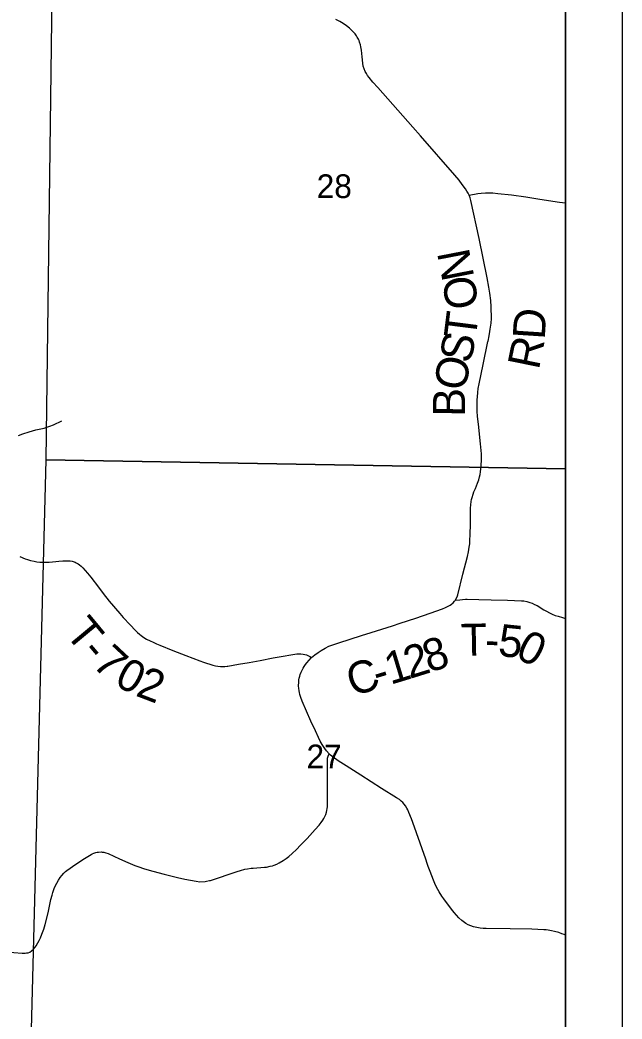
# Model space of a CAD drawing. Extents: x 0 to 34, y 0 to 22.
# Drawn here: x 7.936 to 9, y 15.399 to 17.164 of the extents above; entities that cross this region are included whole.
import ezdxf

# ---------------------------------------------------------------- set-up
doc = ezdxf.new("R2010")
doc.units = 0
for name, color, linetype in [('GM_X_Corporation', 7, 'Continuous'), ('GM_X_County_Road', 7, 'Continuous'), ('GM_X_County_Road_Text', 7, 'Continuous'), ('GM_X_Section_Text', 7, 'Continuous'), ('GM_X_Township_Road', 7, 'Continuous'), ('GM_X_Township_Road_Text', 7, 'Continuous'), ('GM_X_Township_Text', 7, 'Continuous'), ('SH_Data', 7, 'Continuous')]:
    doc.layers.add(name, color=color, linetype=linetype)

msp = doc.modelspace()

# ---------------------------------------------------------------- linework, layer by layer
at = {"layer": 'GM_X_Corporation'}
for points in [[(7.1227, 14.1), (8.9, 14.1), (8.9, 20.9), (7.231, 20.9), (7.2244, 20.2649), (7.1982, 19.2496), (7.1981, 19.2461), (7.1974, 19.2018), (7.1957, 19.0991), (7.1992, 18.9556), (7.197, 18.9465), (7.1949, 18.8464), (7.1846, 18.5133), (7.1817, 18.3306), (7.1804, 18.2238), (7.1572, 17.4131), (7.1504, 16.6562), (7.1434, 16.3848), (7.1318, 15.4937)], [(8.9, 16.3711), (8.9, 17.3865), (7.9945, 17.3927), (7.9815, 16.3875)], [(8.9, 15.3661), (8.9, 16.3711), (7.9815, 16.3875), (7.9552, 15.3809)]]:
    msp.add_lwpolyline(points, close=True, dxfattribs=at)
at = {"layer": 'GM_X_County_Road'}
for points in [[(8.7297, 16.8547), (8.7277, 16.8587), (8.7258, 16.8622), (8.7235, 16.8659), (8.7175, 16.8738), (8.7119, 16.8815), (8.7045, 16.8904), (8.6435, 16.9599), (8.6301, 16.9751), (8.5681, 17.045), (8.5597, 17.0546), (8.553, 17.0629), (8.5502, 17.0665), (8.548, 17.0698), (8.5461, 17.0734), (8.5441, 17.078), (8.5426, 17.0829), (8.5417, 17.0879), (8.5407, 17.0994), (8.5401, 17.1053), (8.5394, 17.111), (8.5383, 17.1168), (8.5375, 17.1203), (8.536, 17.1253), (8.535, 17.128), (8.5339, 17.1304), (8.5318, 17.1343), (8.5307, 17.1361), (8.528, 17.1399), (8.523, 17.1454), (8.5179, 17.1497), (8.5127, 17.1539), (8.5069, 17.1579), (8.501, 17.1615), (8.4942, 17.1652)], [(8.7297, 16.8547), (8.7453, 16.8577), (8.7508, 16.8584), (8.7585, 16.8589), (8.7671, 16.859), (8.7718, 16.8588), (8.7805, 16.8581), (8.8047, 16.8553), (8.8297, 16.8518), (8.8548, 16.848), (8.8897, 16.8427), (8.9, 16.8414)], [(8.9, 15.5472), (8.8974, 15.5484), (8.8936, 15.55), (8.8884, 15.5519), (8.8805, 15.5542), (8.8753, 15.5554), (8.8696, 15.5564), (8.8658, 15.5569), (8.8619, 15.5571), (8.8403, 15.5578), (8.8021, 15.5584), (8.7595, 15.5593), (8.7544, 15.5595), (8.7492, 15.56), (8.7434, 15.561), (8.7376, 15.5624), (8.7327, 15.5639), (8.7281, 15.5658), (8.7239, 15.568), (8.7214, 15.5697), (8.717, 15.5731), (8.7113, 15.5781), (8.7033, 15.5873), (8.6985, 15.5934), (8.685, 15.6114), (8.6814, 15.6166), (8.6765, 15.6241), (8.6722, 15.6323), (8.6692, 15.6387), (8.6667, 15.6446), (8.6608, 15.6597), (8.6595, 15.6631), (8.6574, 15.669), (8.6557, 15.6739), (8.6531, 15.6819), (8.6369, 15.7282), (8.6333, 15.7384), (8.6277, 15.7533), (8.6233, 15.764), (8.6211, 15.7687), (8.6194, 15.7718), (8.6169, 15.7762), (8.6147, 15.7792), (8.6124, 15.7818), (8.6098, 15.7841), (8.6063, 15.7869), (8.6012, 15.7903), (8.5747, 15.8068), (8.5383, 15.8304), (8.5123, 15.8465), (8.4981, 15.8557), (8.4891, 15.8621), (8.4847, 15.8654), (8.482, 15.8676), (8.4777, 15.8729), (8.4744, 15.8775), (8.4697, 15.8846), (8.4666, 15.8903), (8.4635, 15.8966), (8.458, 15.9086), (8.4501, 15.9257), (8.4345, 15.9609), (8.4319, 15.9676), (8.4305, 15.9726), (8.4297, 15.976), (8.4291, 15.9793), (8.4284, 15.9836), (8.4282, 15.9874), (8.4284, 15.9951), (8.4288, 15.9985), (8.4293, 16.0013), (8.4303, 16.0052), (8.4312, 16.0081), (8.4328, 16.0124), (8.4349, 16.0167), (8.4365, 16.0194), (8.4381, 16.0221), (8.4406, 16.0258), (8.4427, 16.0285), (8.4467, 16.0334), (8.451, 16.0378), (8.457, 16.0428), (8.4627, 16.0468), (8.4681, 16.0504), (8.475, 16.0544), (8.4818, 16.0578), (8.4904, 16.0611), (8.4995, 16.0642), (8.5392, 16.0771), (8.5563, 16.0824), (8.5943, 16.0941), (8.608, 16.0985), (8.6356, 16.1077), (8.6609, 16.1162), (8.6827, 16.1238), (8.6879, 16.1261), (8.6925, 16.1285), (8.6959, 16.1305), (8.6986, 16.1324), (8.7015, 16.1349), (8.7041, 16.1377), (8.7053, 16.1393), (8.7064, 16.1413), (8.7084, 16.1454), (8.7096, 16.149), (8.7184, 16.185), (8.7267, 16.2163), (8.7285, 16.2245), (8.7299, 16.2327), (8.7307, 16.239), (8.7311, 16.2443), (8.7317, 16.2561), (8.7319, 16.273), (8.7318, 16.2981), (8.7319, 16.3019), (8.7324, 16.3078), (8.7333, 16.3138), (8.7341, 16.3173), (8.735, 16.321), (8.7368, 16.3267), (8.7382, 16.3307), (8.7409, 16.3365), (8.7428, 16.3411), (8.7446, 16.3461), (8.7467, 16.3522), (8.7481, 16.3572), (8.7491, 16.3614), (8.7499, 16.3662), (8.7505, 16.3712), (8.7512, 16.3792), (8.7515, 16.3856), (8.7513, 16.398), (8.7499, 16.4153), (8.746, 16.4502), (8.7447, 16.464), (8.7441, 16.4733), (8.7437, 16.4835), (8.744, 16.4935), (8.7443, 16.4984), (8.7451, 16.5065), (8.7459, 16.5133), (8.7473, 16.5217), (8.7543, 16.5557), (8.763, 16.5966), (8.7632, 16.5972), (8.765, 16.6066), (8.7664, 16.6139), (8.7671, 16.6181), (8.7684, 16.6285), (8.7691, 16.6368), (8.7687, 16.6575), (8.7679, 16.6688), (8.7664, 16.682), (8.7647, 16.6925), (8.7615, 16.7088), (8.7472, 16.7782), (8.7328, 16.8455), (8.7315, 16.8503), (8.7297, 16.8547)]]:
    msp.add_lwpolyline(points, dxfattribs=at)
at = {"layer": 'GM_X_Township_Road'}
for points in [[(7.9329, 16.4302), (7.9408, 16.4333), (7.9521, 16.437), (7.9636, 16.4401), (7.9723, 16.4422), (7.9783, 16.4435), (7.9831, 16.4447), (7.9883, 16.4466), (7.9947, 16.4493), (8.0097, 16.4562)], [(7.9354, 16.2163), (7.9447, 16.2125), (7.949, 16.2111), (7.9543, 16.2095), (7.9609, 16.208), (7.9656, 16.2071), (7.9709, 16.2065), (7.9756, 16.2064), (7.9869, 16.2066), (7.9931, 16.207), (7.999, 16.2075), (8.0044, 16.208), (8.0111, 16.2087), (8.0159, 16.2089), (8.0212, 16.2089), (8.0244, 16.2087), (8.0278, 16.2082), (8.0298, 16.2075), (8.0331, 16.2064), (8.0352, 16.2055), (8.0387, 16.2034), (8.0411, 16.2017), (8.0437, 16.1997), (8.047, 16.1967), (8.055, 16.1871), (8.0608, 16.1797), (8.0743, 16.1622), (8.0825, 16.1513), (8.0935, 16.1374), (8.1119, 16.1156), (8.1178, 16.1089), (8.1303, 16.0955), (8.1398, 16.0856), (8.1434, 16.0822), (8.1471, 16.0792), (8.1501, 16.0769), (8.1547, 16.0736), (8.1593, 16.0706), (8.1655, 16.0673), (8.1708, 16.0649), (8.1771, 16.0622), (8.1828, 16.0598), (8.2061, 16.0507), (8.229, 16.0417), (8.2536, 16.0324), (8.2599, 16.03), (8.2763, 16.0247), (8.2815, 16.0233), (8.2852, 16.0226), (8.2899, 16.0222), (8.2941, 16.0221), (8.2976, 16.0223), (8.3019, 16.0228), (8.3029, 16.023)], [(8.7053, 16.1393), (8.7133, 16.1402), (8.7179, 16.1406), (8.7231, 16.1409), (8.7263, 16.1409), (8.7467, 16.1408), (8.7685, 16.14), (8.7974, 16.1391), (8.8223, 16.1383), (8.8261, 16.1379), (8.8319, 16.1367), (8.8371, 16.1352), (8.841, 16.1338), (8.8454, 16.1319), (8.8497, 16.1297), (8.862, 16.1222), (8.8762, 16.1148), (8.8818, 16.1125), (8.8868, 16.1109), (8.8945, 16.1085), (8.9, 16.1071)], [(8.3029, 16.023), (8.3219, 16.0261), (8.3409, 16.0291), (8.3602, 16.0328), (8.383, 16.0372), (8.4008, 16.0405), (8.4147, 16.043), (8.4216, 16.0441), (8.4248, 16.0443), (8.428, 16.0444), (8.4321, 16.0443), (8.436, 16.044), (8.439, 16.0435), (8.4424, 16.0426), (8.4457, 16.0412), (8.4483, 16.0397), (8.451, 16.0378)], [(7.9098, 15.5179), (7.9395, 15.5159), (7.9446, 15.5158), (7.9474, 15.5161), (7.9502, 15.5165), (7.953, 15.5177), (7.9559, 15.5196), (7.9596, 15.5227), (7.962, 15.5256), (7.9642, 15.5289), (7.9673, 15.5341), (7.9695, 15.5382), (7.972, 15.543), (7.9744, 15.549), (7.9777, 15.5578), (7.9803, 15.5666), (7.9854, 15.5867), (7.9884, 15.6014), (7.9904, 15.6107), (7.9922, 15.618), (7.9936, 15.6227), (7.9963, 15.6301), (7.9978, 15.6338), (8.0005, 15.6394), (8.0036, 15.6446), (8.0068, 15.6493), (8.0094, 15.6527), (8.0133, 15.6571), (8.0161, 15.6597), (8.0182, 15.6617), (8.0341, 15.6731), (8.0494, 15.6828), (8.0613, 15.6898), (8.0631, 15.6909), (8.0659, 15.6921), (8.0697, 15.6934), (8.0721, 15.6939), (8.0746, 15.6943), (8.0789, 15.6945), (8.0808, 15.6944), (8.0837, 15.694), (8.0875, 15.693), (8.0913, 15.6915), (8.1015, 15.687), (8.1114, 15.6824), (8.1263, 15.6758), (8.1384, 15.6708), (8.1456, 15.6682), (8.1538, 15.6653), (8.16, 15.6633), (8.1705, 15.6603), (8.1905, 15.6552), (8.2139, 15.6494), (8.2272, 15.6467), (8.2471, 15.6426), (8.2533, 15.6419), (8.2629, 15.6422), (8.2656, 15.6426), (8.2707, 15.6438), (8.2723, 15.6443), (8.3198, 15.6597), (8.3255, 15.6617), (8.3332, 15.6638), (8.3381, 15.6649), (8.3446, 15.6658), (8.3479, 15.6661), (8.368, 15.6675), (8.3716, 15.6679), (8.3778, 15.6691), (8.382, 15.6702), (8.3851, 15.6713), (8.3896, 15.6731), (8.394, 15.6753), (8.4006, 15.6793), (8.4062, 15.6832), (8.4107, 15.6866), (8.417, 15.6916), (8.4245, 15.6987), (8.4318, 15.7063), (8.4431, 15.7181), (8.4577, 15.7343), (8.4647, 15.7421), (8.4679, 15.7463), (8.4708, 15.7506), (8.4727, 15.7537), (8.4746, 15.757), (8.4762, 15.7608), (8.4775, 15.7649), (8.4783, 15.7678), (8.4789, 15.7712), (8.4793, 15.7745), (8.4795, 15.7777), (8.4794, 15.7951), (8.479, 15.8085), (8.4794, 15.8601), (8.4803, 15.8637), (8.482, 15.8676)]]:
    msp.add_lwpolyline(points, dxfattribs=at)
at = {"layer": 'GM_X_Township_Text'}
msp.add_lwpolyline([(7.1227, 14.1), (8.9, 14.1), (8.9, 19.2243), (7.7835, 19.2432), (7.6914, 19.2442), (7.3421, 19.2478), (7.2323, 19.2489), (7.1982, 19.2496)], dxfattribs=at)
at = {"layer": 'SH_Data'}
for p, q in [((9, 21), (9, 14)), ((8.9, 20.9), (8.9, 14.1))]:
    msp.add_line(p, q, dxfattribs=at)

# ---------------------------------------------------------------- texts
at = {"layer": 'GM_X_County_Road_Text'}
for s, rotation, p in [('N', 101.0152, (8.739, 16.7103)), ('O', 97.7259, (8.7463, 16.6573)), ('T', 82.8184, (8.741, 16.599)), ('D', 86.276, (8.8632, 16.5988)), ('S', 77.4903, (8.7317, 16.5559)), ('R', 78.483, (8.8528, 16.5449)), ('O', 79.1637, (8.7224, 16.5072)), ('B', 89.5355, (8.7223, 16.4633)), ('2', 17.2927, (8.6243, 15.9999)), ('8', 18.3239, (8.6587, 16.0107)), ('1', 16.8925, (8.5904, 15.9896)), ('C', 18.0067, (8.5239, 15.9685)), ('-', 16.8907, (8.568, 15.9828))]:
    msp.add_text(s, height=0.0568, rotation=rotation, dxfattribs=at).set_placement(p)
at = {"layer": 'GM_X_Section_Text'}
for s, p in [('28', (8.4601, 16.8498)), ('27', (8.4422, 15.8423))]:
    msp.add_text(s, height=0.04186, rotation=0, dxfattribs=at).set_placement(p)
at = {"layer": 'GM_X_Township_Road_Text'}
for s, rotation, p in [('T', 309.7167, (8.0138, 16.0802)), ('T', 1.1122, (8.7155, 16.0406)), ('5', 354.1641, (8.7795, 16.0411)), ('0', 332.9602, (8.809, 16.0391)), ('7', 316.9869, (8.0614, 16.0239)), ('-', 359.0437, (8.7575, 16.0414)), ('-', 310.1851, (8.0413, 16.0471)), ('0', 332.1522, (8.1003, 15.9906)), ('2', 339.151, (8.1382, 15.9711))]:
    msp.add_text(s, height=0.0568, rotation=rotation, dxfattribs=at).set_placement(p)

doc.saveas('drawing.dxf')
